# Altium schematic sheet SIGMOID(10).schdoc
size 297 x 209 mm; Symbol: Drawing-Symbol_A4; @Project Name: Inverted_MAML_6x6; @Page Count: 1; @Update Date: 2026-06-14; @Create Date: 2026-06-14; @Schematic Name: Schematic1; @Page No: 1; @Page Name: P1; Company: EasyEDA.com; Version: V1.0; Page Size: A4; Drawn: Olle Welin; Device: Drawing-Symbol_A4; @Create Time: 16:51:10; @Update Time: 16:51:10; Border: 1; Width: 1170; Height: 825; Region Start: 1; X Region Count: 6; Y Region Count: 4; Blade Width: 10; Title Block Position: 3
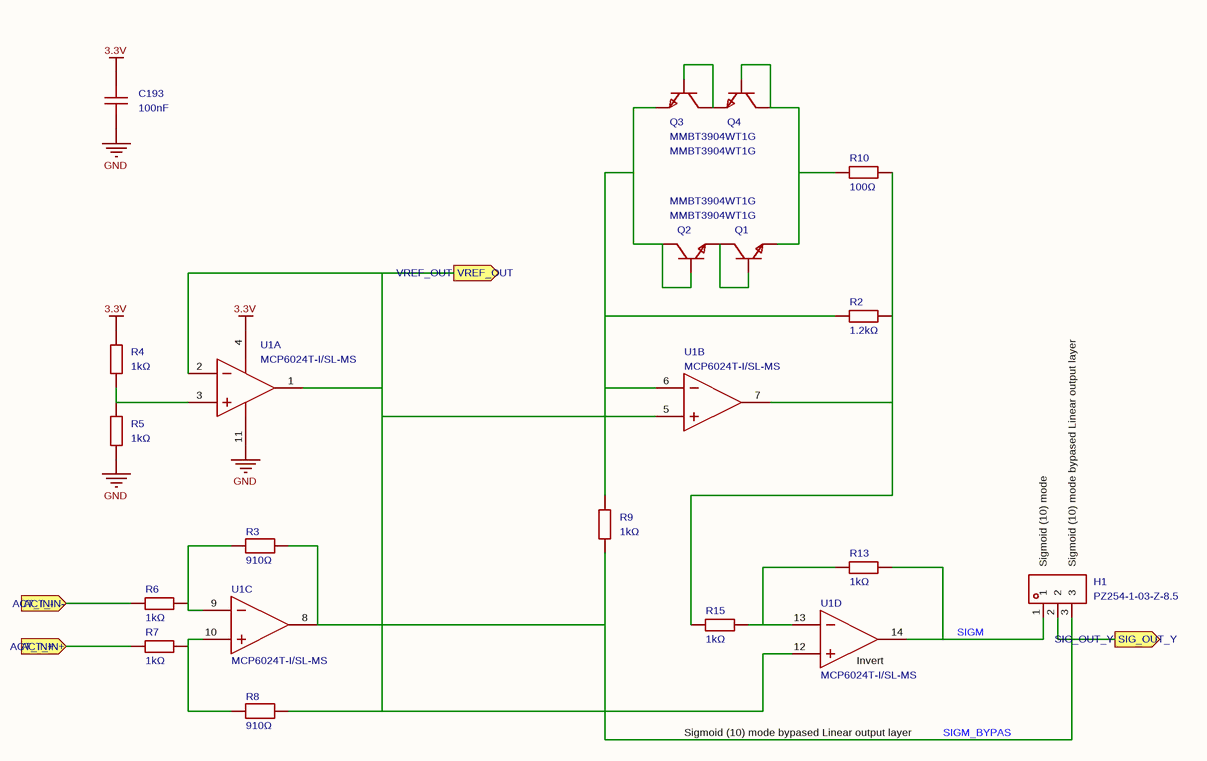
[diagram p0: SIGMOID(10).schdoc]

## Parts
C193  100nF  [C0402]
H1  PZ254-1-03-Z-8.5  [HDR-TH_03P-P2.54-V-M]
Q1  MMBT3904WT1G  [SC-70-3_L2.1-W1.3-P1.30-LS2.1-BR]
Q2  MMBT3904WT1G  [SC-70-3_L2.1-W1.3-P1.30-LS2.1-BR]
Q3  MMBT3904WT1G  [SC-70-3_L2.1-W1.3-P1.30-LS2.1-BR]
Q4  MMBT3904WT1G  [SC-70-3_L2.1-W1.3-P1.30-LS2.1-BR]
R2  1.2kΩ  [R0402]
R3  910Ω  [R0402]
R4  1kΩ  [R0402]
R5  1kΩ  [R0402]
R6  1kΩ  [R0402]
R7  1kΩ  [R0402]
R8  910Ω  [R0402]
R9  1kΩ  [R0402]
R10  100Ω  [R0402]
R13  1kΩ  [R0402]
R15  1kΩ  [R0402]
U1  MCP6024T-I/SL-MS  [SOIC-14_L8.7-W3.9-P1.27-LS6.0-BL-1]  (parts A,B,C,D of 4)

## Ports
ACT_IN+ (in), ACT_IN- (in), SIG_OUT_Y (out), VREF_OUT (out)

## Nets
3.3V: C193.2 R4.2 U1.4(V+)
GND: C193.1 R5.1 U1.11(V-)
ACT_IN+: R7.2 ; port ACT_IN+
ACT_IN-: R6.2 ; port ACT_IN-
SIG_OUT_Y: H1.2 ; port SIG_OUT_Y
SIGM: H1.1 R13.2 U1.14(OUT4)
SIGM_BYPAS: H1.3 R3.2 R9.2 U1.8(OUT3)
VREF_OUT: R8.2 U1.1(OUT1) U1.2(IN1-) U1.5(IN2+) U1.12(IN4+) ; port VREF_OUT
NetQ1_1: Q1.1(B) Q1.3(C) Q2.2(E)
NetQ1_2: Q1.2(E) Q4.1(B) Q4.3(C) R10.2
NetQ2_1: Q2.1(B) Q2.3(C) Q3.2(E) R2.1 R9.1 U1.6(IN2-)
NetQ3_1: Q3.1(B) Q3.3(C) Q4.2(E)
NetR2_2: R2.2 R10.1 R15.1 U1.7(OUT2)
NetR3_1: R3.1 R6.1 U1.9(IN3-)
NetR4_1: R4.1 R5.2 U1.3(IN1+)
NetR7_1: R7.1 R8.1 U1.10(IN3+)
NetR13_1: R13.1 R15.2 U1.13(IN4-)

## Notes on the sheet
- (near H1) Sigmoid (10) mode
- (near H1) Sigmoid (10) mode bypased Linear output layer
- (near U1) Invert
- Sigmoid (10) mode bypased Linear output layer

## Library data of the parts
C193 = CL05B104KO5NNNC: Capacitance:100nF Tolerance:±10% Tolerance:±10% Voltage Rating:16V Temperature Coefficient:X7R; Manufacturer: SAMSUNG(三星); 3D Model: b7d13df3e9464d7a99d0651d1a5b4d570819f05c4eef4c71ace90d822a990e87; 3D Model Transform: 39.37,19.685,0,0,0,0,0,0,0; Tolerance: ±10%; Voltage Rating: 16V; Temperature Coefficient: X7R; AddInBom: yes; ModelName: C0402_L1.0-W0.5-H0.5
H1 = PZ254-1-03-Z-8.5_C2894926: Pin Structure:1x3P Pitch:2.54mm Row Spacing:- Circluar Pins/Square Pins:Pin Header Mounting Type:Through Hole Number of Rows:1 Number of Pins:3P Current Rating:3A Voltage Rating (Max):- Length of Mating Pin:6mm Insulation Height:2.5mm Length of End Connec; Manufacturer: HCTL(华灿天禄); AddInBom: yes; ModelId: 4088faa0d9ee454db92354e880b104140819f05c4eef4c71ace90d822a990e87; ModelTransform: 299.999,98.425,0,0,0,0,0,0,-118.11; Pin Structure: 1x3P; Pitch: 2.54mm; Current Rating: 3A
Q1-Q4 = MMBT3904WT1G: type:NPN Current - Collector(Ic):200mA Collector - Emitter Voltage VCEO:40V Pd - Power Dissipation:150mW DC Current Gain:40@0.1mA,1.0V DC Current Gain:40@0.1mA,1.0V Transition frequency(fT):300MHz Current - Collector Cutoff:50nA Vce Saturation(VCE(sat)):2; Manufacturer: onsemi(安森美); 3D Model: 13e0912de9fe4b51b1f46985f9be7482; 3D Model Transform: 82.677,78.74,0,180,0,0,-0.0025,0,0; type: NPN; Current - Collector(Ic): 200mA; Collector - Emitter Voltage VCEO: 40V; Pd - Power Dissipation: 150mW; Transition frequency(fT): 300MHz; Current - Collector Cutoff: 50nA; Vce Saturation(VCE(sat)): 200mV; Emitter-Base Voltage(Vebo): 6V; AddInBom: yes; ModelName: SC-70-3_L2.0-W1.3-H1.0-P0.65
R2 = 0402WGF1201TCE: Type:Thick Film Resistor Resistance:1.2kΩ Tolerance:±1% Tolerance:±1% Power(Watts):62.5mW Voltage-Supply(Max):50V Temperature Coefficient:±100ppm/℃ Temperature Coefficient:±100ppm/℃ Operating Temperature:-55℃~+155℃ Operating Temperature:-55℃~+155℃; Manufacturer: UNI-ROYAL(厚声); AddInBom: yes; ModelId: efdecb7dae4442949d28eecaf748420f0819f05c4eef4c71ace90d822a990e87; ModelName: R0402_L1.0-W0.5-H0.4; ModelTransform: 39.37,19.685,0,0,0,0,0,0,0; Tolerance: ±1%; Power(Watts): 62.5mW; Voltage-Supply(Max): 50V
R3 R8 = SCR0402J910R: Type:Thick Film Resistor Resistance:910Ω Tolerance:±5% Tolerance:±5% Power(Watts):62.5mW Voltage-Supply(Max):50V Temperature Coefficient:±200ppm/℃ Temperature Coefficient:±200ppm/℃ Operating Temperature:-55℃~+155℃ Operating Temperature:-55℃~+155℃; Manufacturer: VO(翔胜); AddInBom: yes; ModelId: efdecb7dae4442949d28eecaf748420f0819f05c4eef4c71ace90d822a990e87; ModelName: R0402_L1.0-W0.5-H0.4; ModelTransform: 39.37,19.685,0,0,0,0,0,0,0; Tolerance: ±5%; Power(Watts): 62.5mW; Voltage-Supply(Max): 50V
R4-R7 R9 = 0402WGF1001TCE: Type:Thick Film Resistor Resistance:1kΩ Tolerance:±1% Tolerance:±1% Power(Watts):62.5mW Voltage-Supply(Max):50V Temperature Coefficient:±100ppm/℃ Temperature Coefficient:±100ppm/℃ Operating Temperature:-55℃~+155℃ Operating Temperature:-55℃~+155℃; Manufacturer: UNI-ROYAL(厚声); AddInBom: yes; ModelId: efdecb7dae4442949d28eecaf748420f0819f05c4eef4c71ace90d822a990e87; ModelName: R0402_L1.0-W0.5-H0.4; ModelTransform: 39.37,19.685,0,0,0,0,0,0,0; Tolerance: ±1%; Power(Watts): 62.5mW; Voltage-Supply(Max): 50V
R10 = 0402WGF1000TCE: Type:Thick Film Resistors Resistance: Tolerance:±1% Tolerance:±1% Power(Watts): Overload Voltage (Max): Temperature Coefficient:±200ppm/℃ Temperature Coefficient:±200ppm/℃ Operating Temperature Range:-55℃~+155℃ Operating Temperature Range:-55℃~+155℃; Manufacturer: UNI-ROYAL(厚声); 3D Model: efdecb7dae4442949d28eecaf748420f0819f05c4eef4c71ace90d822a990e87; 3D Model Transform: 39.37,19.685,0,0,0,0,0,0,0; Tolerance: ±1%; AddInBom: yes; ModelName: R0402_L1.0-W0.5-H0.4
R13 R15 = 0402WGF1001TCE: Type:Thick Film Resistor Resistance:1kΩ Tolerance:±1% Tolerance:±1% Power(Watts):62.5mW Voltage-Supply(Max):50V Temperature Coefficient:±100ppm/℃ Temperature Coefficient:±100ppm/℃ Operating Temperature:-55℃~+155℃ Operating Temperature:-55℃~+155℃; Manufacturer: UNI-ROYAL(厚声); 3D Model: efdecb7dae4442949d28eecaf748420f0819f05c4eef4c71ace90d822a990e87; 3D Model Transform: 39.37,19.685,0,0,0,0,0,0,0; Tolerance: ±1%; Power(Watts): 62.5mW; Voltage-Supply(Max): 50V; AddInBom: yes; ModelName: R0402_L1.0-W0.5-H0.4
U1 = MCP6024T-I/SL-MS: Manufacturer: MSKSEMI(美森科); Relevance: []; AddInBom: yes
